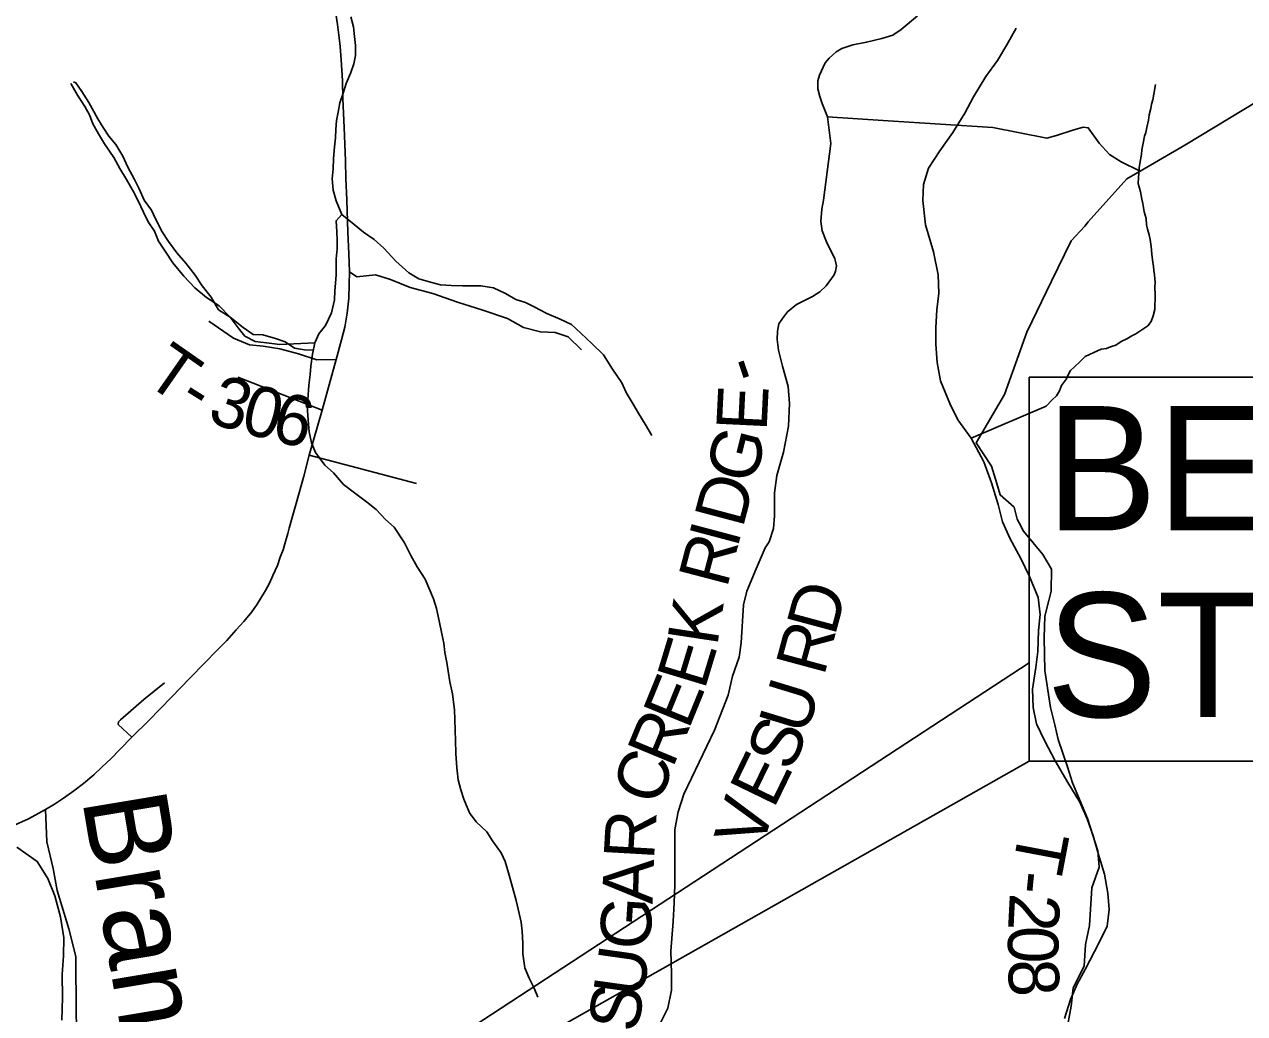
# Model space of a CAD drawing. Extents: x 0 to 34, y 0 to 22.
# Drawn here: x 4.76 to 6.132, y 17.398 to 18.512 of the extents above; entities that cross this region are included whole.
import ezdxf

# ---------------------------------------------------------------- set-up
doc = ezdxf.new("R2010")
doc.units = 0
for name, color, linetype in [('GM_X_County_Road', 7, 'Continuous'), ('GM_X_County_Road_Text', 7, 'Continuous'), ('GM_X_Minor_River', 7, 'Continuous'), ('GM_X_Minor_River_Text', 7, 'Continuous'), ('GM_X_State_Route', 7, 'Continuous'), ('GM_X_Township_Road', 7, 'Continuous'), ('GM_X_Township_Road_Text', 7, 'Continuous'), ('SH_Masking', 7, 'Continuous'), ('SH_Text', 7, 'Continuous')]:
    doc.layers.add(name, color=color, linetype=linetype)

msp = doc.modelspace()

# ---------------------------------------------------------------- linework, layer by layer
at = {"layer": 'GM_X_County_Road'}
for points in [[(5.4754, 17.3881), (5.4834, 17.4045), (5.4878, 17.4247), (5.4878, 17.4436), (5.487, 17.4689), (5.4895, 17.5023), (5.4907, 17.5233), (5.4915, 17.5433), (5.4915, 17.6057), (5.4951, 17.6257), (5.5016, 17.6455), (5.5361, 17.7175), (5.5512, 17.7568), (5.5561, 17.7783), (5.5639, 17.7996), (5.5661, 17.8158), (5.5688, 17.8587), (5.5725, 17.8738), (5.583, 17.8991), (5.5932, 17.9227), (5.5976, 17.9295), (5.6023, 17.9445), (5.6037, 17.9589), (5.6037, 17.9846), (5.6061, 18.0042), (5.6138, 18.0306), (5.6191, 18.0598), (5.6204, 18.0854), (5.6188, 18.1042), (5.6126, 18.1271), (5.608, 18.1451), (5.6067, 18.1571), (5.6068, 18.1665), (5.6085, 18.175), (5.6124, 18.1811), (5.6183, 18.1883), (5.6282, 18.1967), (5.6463, 18.2056), (5.6547, 18.2111), (5.6617, 18.2176), (5.6706, 18.2301), (5.6723, 18.2343), (5.6731, 18.2402), (5.6727, 18.2437), (5.6713, 18.248), (5.6622, 18.2673), (5.6571, 18.2795), (5.6556, 18.2902), (5.6566, 18.3039), (5.6587, 18.3143), (5.6668, 18.378), (5.6632, 18.4081), (5.6573, 18.423), (5.6544, 18.4308), (5.6523, 18.4393), (5.6521, 18.4486), (5.6543, 18.4549), (5.6605, 18.4687), (5.665, 18.474), (5.6729, 18.481), (5.6794, 18.485), (5.6918, 18.4889), (5.7072, 18.4919), (5.7244, 18.4962), (5.7366, 18.4997), (5.7461, 18.5063), (5.7644, 18.5215)], [(4.8803, 17.7097), (4.8651, 17.724), (4.8655, 17.727), (4.8678, 17.7292), (4.8941, 17.7522), (4.9172, 17.7707)], [(4.7834, 17.6281), (4.7935, 17.6343), (4.8035, 17.6409), (4.8152, 17.6492), (4.826, 17.6576), (4.8378, 17.6673), (4.8467, 17.6757), (4.8571, 17.6858), (4.8669, 17.6956), (4.8803, 17.7097)], [(4.8886, 16.9624), (4.8894, 16.9787), (4.8887, 17.0141), (4.8892, 17.0726), (4.8884, 17.1231), (4.8823, 17.1597), (4.875, 17.1887), (4.8711, 17.2013), (4.8646, 17.2132), (4.8547, 17.2313), (4.8468, 17.2482), (4.831, 17.2926), (4.8221, 17.3179), (4.8198, 17.3327), (4.8178, 17.3985), (4.8173, 17.4627), (4.8096, 17.494), (4.7965, 17.5369), (4.7918, 17.5617), (4.7849, 17.5918), (4.7834, 17.6281)]]:
    msp.add_lwpolyline(points, dxfattribs=at)
at = {"layer": 'GM_X_Minor_River'}
for points in [[(5.1268, 18.5206), (5.1299, 18.5092), (5.131, 18.4982), (5.1321, 18.4883), (5.1321, 18.4769), (5.1302, 18.4674), (5.1268, 18.458), (5.1215, 18.4454), (5.1181, 18.4344), (5.1144, 18.4238), (5.1125, 18.4132), (5.1106, 18.4037), (5.1098, 18.3938), (5.1094, 18.3843), (5.1083, 18.3741), (5.1075, 18.3611), (5.1068, 18.3494), (5.106, 18.338), (5.1068, 18.3255), (5.1102, 18.3133), (5.1166, 18.2981), (5.1306, 18.2868), (5.1412, 18.278), (5.1529, 18.2697), (5.1638, 18.2602), (5.1774, 18.2454), (5.1922, 18.2325), (5.2035, 18.2257), (5.2164, 18.2219), (5.2277, 18.2188), (5.2398, 18.2181), (5.2523, 18.2177), (5.2731, 18.2177), (5.2874, 18.2155), (5.301, 18.209), (5.3124, 18.2022), (5.3233, 18.1988), (5.3332, 18.1942), (5.3475, 18.1866), (5.3623, 18.1802), (5.3751, 18.1741), (5.3857, 18.1643), (5.3982, 18.1525), (5.411, 18.14), (5.4212, 18.124), (5.4318, 18.1085), (5.4367, 18.0978), (5.4435, 18.0864), (5.4507, 18.0735), (5.4579, 18.0618), (5.4655, 18.0492)], [(5.8756, 18.5077), (5.8649, 18.4888), (5.8543, 18.4714), (5.8413, 18.4532), (5.8276, 18.4304), (5.8177, 18.4122), (5.804, 18.3903), (5.7896, 18.3698), (5.7767, 18.3501), (5.7713, 18.3319), (5.7705, 18.3137), (5.7734, 18.2864), (5.7824, 18.256), (5.7877, 18.2301), (5.7884, 18.2096), (5.786, 18.1906), (5.7852, 18.1709), (5.7852, 18.1519), (5.7866, 18.1314), (5.7903, 18.1109), (5.8008, 18.0851), (5.8099, 18.0668), (5.8249, 18.0463), (5.8392, 18.0196), (5.8475, 17.9961), (5.855, 17.9717), (5.8602, 17.952), (5.8685, 17.933), (5.8806, 17.9109), (5.8903, 17.8904), (5.9001, 17.8668), (5.9023, 17.8478), (5.9007, 17.8296), (5.8999, 17.8061), (5.8976, 17.7879), (5.8937, 17.7636), (5.8944, 17.7431), (5.8982, 17.7248), (5.9072, 17.7058), (5.9192, 17.683), (5.9335, 17.6587), (5.9471, 17.6366), (5.9554, 17.6176), (5.9621, 17.5986), (5.9689, 17.575), (5.9748, 17.5553), (5.9786, 17.534), (5.98, 17.5158), (5.9777, 17.4968), (5.9686, 17.4778), (5.9533, 17.449), (5.9442, 17.4316), (5.9366, 17.4142), (5.9297, 17.3929)], [(5.0863, 18.1535), (5.047, 18.1516), (5.0319, 18.1534), (5.0191, 18.155), (5.0077, 18.161), (5.0002, 18.1705), (4.9911, 18.1823), (4.9786, 18.1952), (4.9646, 18.2047), (4.9514, 18.2153), (4.9389, 18.2286), (4.9265, 18.2437), (4.9178, 18.2566), (4.9106, 18.268), (4.9061, 18.2794), (4.8989, 18.2897), (4.8936, 18.3007), (4.8875, 18.3132), (4.8819, 18.3242), (4.8743, 18.3375), (4.8671, 18.3496), (4.86, 18.3622), (4.8497, 18.3777), (4.8429, 18.3887), (4.8365, 18.4001), (4.8327, 18.41), (4.8275, 18.4195), (4.8191, 18.4324), (4.8116, 18.4453)], [(5.0846, 18.1454), (5.0748, 18.1456), (5.0635, 18.1476), (5.0529, 18.1548), (5.0419, 18.1583), (5.0279, 18.1625), (5.0169, 18.1629), (5.0056, 18.1709), (4.9909, 18.1824), (4.978, 18.1908), (4.9697, 18.2048), (4.9596, 18.2178), (4.9516, 18.2296), (4.9411, 18.2433), (4.9309, 18.2547), (4.9215, 18.2677), (4.9147, 18.2783), (4.9071, 18.2931), (4.9026, 18.303), (4.8943, 18.3141), (4.8887, 18.327), (4.8834, 18.3373), (4.8759, 18.3513), (4.8702, 18.3635), (4.8623, 18.3768), (4.8544, 18.3863), (4.848, 18.3959), (4.842, 18.4057), (4.8322, 18.424), (4.8242, 18.4366), (4.8175, 18.4461), (4.8148, 18.4472)], [(5.8249, 18.0463), (5.9092, 18.0823), (5.9158, 18.0894), (5.9208, 18.0939), (5.9243, 18.0995), (5.9266, 18.1056), (5.9321, 18.1131), (5.934, 18.1176), (5.9364, 18.1225), (5.9406, 18.1262), (5.948, 18.133), (5.953, 18.1382), (5.9629, 18.1426), (5.9709, 18.1463), (5.977, 18.1473), (5.9816, 18.1491), (5.9877, 18.1509), (5.9934, 18.155), (5.9999, 18.1579), (6.0056, 18.1613), (6.0102, 18.1635), (6.0236, 18.1727), (6.0275, 18.1776), (6.0295, 18.1841), (6.0315, 18.1912), (6.0318, 18.2076), (6.0316, 18.216), (6.0317, 18.2213), (6.0314, 18.2255), (6.0311, 18.23), (6.0304, 18.235), (6.0301, 18.2399), (6.0291, 18.2441), (6.0281, 18.2533), (6.0275, 18.262), (6.0261, 18.2697), (6.0251, 18.275), (6.0233, 18.2815), (6.0222, 18.2865), (6.0216, 18.2933), (6.0195, 18.301), (6.0188, 18.3059), (6.0181, 18.3105), (6.017, 18.3151), (6.0153, 18.3235), (6.0142, 18.3277), (6.0128, 18.333), (6.0129, 18.3395), (6.0134, 18.3436), (6.0139, 18.3505), (6.0151, 18.3577), (6.0164, 18.3656), (6.0169, 18.3709), (6.0185, 18.3781), (6.0198, 18.3861), (6.0214, 18.3903), (6.0226, 18.3959), (6.0243, 18.4043), (6.0252, 18.4103), (6.0268, 18.4172), (6.0276, 18.4221), (6.0292, 18.427), (6.0305, 18.4334), (6.0322, 18.4444)], [(5.1166, 18.2981), (5.1102, 18.2909), (5.1109, 18.2784), (5.1113, 18.2689), (5.1113, 18.2594), (5.1105, 18.248), (5.1102, 18.2298), (5.109, 18.212), (5.1083, 18.2021), (5.1049, 18.1873), (5.0984, 18.1732), (5.0909, 18.1637), (5.0863, 18.1535), (5.0837, 18.1409), (5.0818, 18.1273), (5.081, 18.1178), (5.0795, 18.106), (5.0784, 18.0893), (5.078, 18.0768), (5.0788, 18.0669), (5.0799, 18.0532), (5.0825, 18.0411), (5.0871, 18.0301), (5.0977, 18.016), (5.1075, 18.0073), (5.1184, 17.994), (5.1309, 17.9845), (5.1445, 17.9747), (5.1555, 17.9659), (5.1657, 17.9545), (5.1755, 17.9462), (5.1872, 17.9284), (5.1944, 17.9143), (5.2016, 17.9014), (5.2103, 17.8874), (5.2197, 17.8653), (5.2231, 17.8543), (5.2261, 17.8407), (5.2292, 17.8259), (5.2314, 17.8156), (5.2326, 17.805), (5.2348, 17.7936), (5.2363, 17.7841), (5.2382, 17.7719), (5.2413, 17.7583), (5.2435, 17.74), (5.2439, 17.7302), (5.2443, 17.7169), (5.2446, 17.7063), (5.245, 17.6911), (5.2462, 17.6751), (5.2477, 17.6618), (5.2507, 17.6504), (5.2541, 17.6398), (5.2605, 17.6246), (5.2677, 17.6144), (5.2798, 17.603), (5.2862, 17.5931), (5.296, 17.5795), (5.3006, 17.5696), (5.3043, 17.5571), (5.3089, 17.5407), (5.313, 17.5259), (5.3161, 17.5111), (5.3183, 17.5013), (5.3195, 17.4914), (5.3202, 17.4774), (5.3202, 17.4656), (5.3225, 17.45), (5.3274, 17.4383), (5.3331, 17.4272), (5.3372, 17.417)], [(4.8016, 17.3909), (4.8024, 17.4167), (4.8021, 17.4426), (4.8036, 17.4636), (4.804, 17.4837), (4.8003, 17.5073), (4.7936, 17.5309), (4.786, 17.5504), (4.774, 17.5698), (4.7509, 17.5858)]]:
    msp.add_lwpolyline(points, dxfattribs=at)
at = {"layer": 'GM_X_State_Route'}
msp.add_line((5.0558, 17.9388), (5.0563, 17.9405), dxfattribs=at)
for points in [[(5.0563, 17.9405), (5.0575, 17.9449), (5.0616, 17.9597), (5.0652, 17.9726), (5.0738, 18.0035), (5.0798, 18.0269), (5.0944, 18.0777), (5.1105, 18.1349), (5.1162, 18.1569), (5.1199, 18.1713), (5.1228, 18.1871), (5.1247, 18.2039), (5.1251, 18.219), (5.1253, 18.2336), (5.1246, 18.2536), (5.1236, 18.2782), (5.1222, 18.3144), (5.1213, 18.3384), (5.1207, 18.3583), (5.1194, 18.396), (5.118, 18.4281), (5.1173, 18.4487), (5.1161, 18.4719), (5.115, 18.487), (5.1138, 18.4968), (5.1118, 18.5119), (5.1082, 18.5365)], [(4.8803, 17.7097), (4.899, 17.7279), (4.9254, 17.7552), (4.9452, 17.7755), (4.9627, 17.7934), (4.9758, 17.8067), (4.9872, 17.8186), (4.9978, 17.8304), (5.0064, 17.8397), (5.0154, 17.8508), (5.0215, 17.8595), (5.0308, 17.8746), (5.0352, 17.883), (5.0392, 17.8916), (5.0442, 17.903), (5.0475, 17.9124), (5.0507, 17.9206), (5.0534, 17.93), (5.0558, 17.9388)], [(4.7834, 17.6281), (4.7935, 17.6343), (4.8035, 17.6409), (4.8152, 17.6492), (4.826, 17.6576), (4.8378, 17.6673), (4.8467, 17.6757), (4.8571, 17.6858), (4.8669, 17.6956), (4.8803, 17.7097)], [(4.7457, 17.6094), (4.7641, 17.6178), (4.7834, 17.6281)]]:
    msp.add_lwpolyline(points, dxfattribs=at)
at = {"layer": 'GM_X_Township_Road'}
for p, q in [((4.9995, 18.1148), (5.0944, 18.0777)), ((5.0798, 18.0269), (5.2006, 17.9951))]:
    msp.add_line(p, q, dxfattribs=at)
for points in [[(5.9566, 18.2896), (6.0001, 18.3383), (6.015, 18.3469), (6.0652, 18.3759), (6.1478, 18.426), (6.2129, 18.4786), (6.2855, 18.5713), (6.333, 18.6514), (6.4207, 18.7391), (6.5069, 18.7924), (6.5513, 18.8198), (6.5583, 18.8242), (6.5605, 18.8253)], [(5.6632, 18.4081), (5.7313, 18.4033), (5.849, 18.3958), (5.91, 18.3838), (5.9209, 18.3868), (5.9392, 18.3929), (5.9509, 18.3964), (5.9566, 18.3956), (5.9688, 18.3781), (5.9806, 18.3655), (5.9936, 18.3572), (6.015, 18.3469)], [(5.8788, 17.9508), (5.8767, 17.9549), (5.8731, 17.9684), (5.8573, 17.9824), (5.8538, 17.9953), (5.8475, 18.0148), (5.8304, 18.041), (5.8624, 18.0953), (5.8875, 18.1654), (5.915, 18.2231), (5.9375, 18.2682), (5.9526, 18.285), (5.9566, 18.2896)], [(5.1253, 18.2336), (5.1334, 18.228), (5.1547, 18.2302), (5.1713, 18.2248), (5.1936, 18.2159), (5.219, 18.2089), (5.247, 18.1992), (5.2754, 18.1903), (5.303, 18.181), (5.3211, 18.1706), (5.3401, 18.1659), (5.3568, 18.1651), (5.3715, 18.1604), (5.3862, 18.1455)], [(5.1105, 18.1349), (5.0884, 18.1344), (5.068, 18.141), (5.0468, 18.1468), (5.0282, 18.1496), (5.0127, 18.1512), (4.9949, 18.1589), (4.967, 18.1781)], [(5.9189, 17.7234), (5.9141, 17.743), (5.9077, 17.7846), (5.9071, 17.8215), (5.9078, 17.846), (5.9123, 17.8636), (5.9147, 17.8741), (5.9153, 17.8987), (5.9053, 17.9151), (5.8837, 17.9414), (5.8788, 17.9508)], [(5.9317, 17.376), (5.9374, 17.4068), (5.9397, 17.4274), (5.9519, 17.4517), (5.9534, 17.4764), (5.958, 17.4977), (5.9607, 17.5402), (5.9687, 17.5634), (5.9672, 17.5817), (5.9558, 17.6182), (5.9388, 17.6581), (5.9331, 17.6764), (5.9228, 17.7072), (5.9189, 17.7234)]]:
    msp.add_lwpolyline(points, dxfattribs=at)
at = {"layer": 'SH_Masking'}
msp.add_lwpolyline([(5.8902, 18.1147), (7.3577, 18.1147), (7.3577, 17.6825), (5.8902, 17.6825)], close=True, dxfattribs=at)
at = {"layer": 'SH_Text'}
for points in [[(5.8902, 18.1147), (7.3577, 18.1147), (7.3577, 17.6825), (5.8902, 17.6825)], [(4.6333, 16.9712), (5.8902, 17.7932), (5.8902, 17.6825)]]:
    msp.add_lwpolyline(points, close=True, dxfattribs=at)

# ---------------------------------------------------------------- texts
at = {"layer": 'GM_X_County_Road_Text'}
for s, rotation, p in [('-', 108.5194, (5.5936, 18.1187)), ('E', 87.2002, (5.5946, 18.0535)), ('G', 75.8337, (5.5806, 17.9929)), ('D', 75.123, (5.5676, 17.9438)), ('I', 75.1189, (5.5616, 17.9212)), ('R', 75.3411, (5.5498, 17.8762)), ('D', 74.9061, (5.6713, 17.8223)), ('K', 81.3362, (5.539, 17.8111)), ('R', 74.8892, (5.6591, 17.7772)), ('E', 73.1005, (5.5247, 17.7618)), ('E', 67.7919, (5.5067, 17.717)), ('U', 73.0048, (5.6393, 17.7105)), ('R', 67.5119, (5.4888, 17.6736)), ('S', 67.4707, (5.6226, 17.6695)), ('C', 69.8875, (5.4729, 17.6304)), ('E', 64.113, (5.6025, 17.6279)), ('V', 73.7436, (5.5894, 17.5823)), ('R', 86.7236, (5.4679, 17.5709)), ('A', 88.2576, (5.4664, 17.5213)), ('G', 86.2843, (5.463, 17.4693)), ('U', 82.0417, (5.4557, 17.4152)), ('S', 80.7083, (5.4492, 17.3759))]:
    msp.add_text(s, height=0.0568, rotation=rotation, dxfattribs=at).set_placement(p)
at = {"layer": 'GM_X_Minor_River_Text'}
msp.add_text('Branch', height=0.09475, rotation=279.4884, dxfattribs=at).set_placement((4.8243, 17.64))
at = {"layer": 'GM_X_Township_Road_Text'}
for s, rotation, p in [('T', 325.0915, (4.893, 18.11)), ('3', 341.9366, (4.9638, 18.0651)), ('-', 327.8683, (4.9303, 18.084)), ('0', 345.6578, (5.001, 18.0532)), ('6', 346.0418, (5.0353, 18.0444)), ('T', 259.2472, (5.8796, 17.6081)), ('-', 264.3347, (5.8709, 17.5609)), ('2', 267.0309, (5.8684, 17.5348)), ('0', 269.1156, (5.8665, 17.4976)), ('8', 272.8571, (5.866, 17.4585))]:
    msp.add_text(s, height=0.0568, rotation=rotation, dxfattribs=at).set_placement(p)
at = {"layer": 'SH_Text'}
for s, p in [('BEGIN PROJECT', (5.9092, 17.9423)), ('STA. 100+40.00', (5.9092, 17.7323))]:
    msp.add_text(s, height=0.14, dxfattribs=at).set_placement(p)

doc.saveas('drawing.dxf')
